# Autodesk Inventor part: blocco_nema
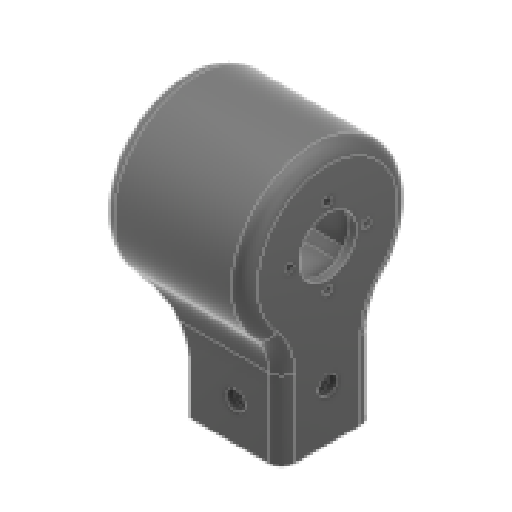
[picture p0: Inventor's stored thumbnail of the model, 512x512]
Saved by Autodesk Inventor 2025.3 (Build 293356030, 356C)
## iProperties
Created: 2026-03
Part Number: blocco_nema
Material: Plastica ABS
Document SubType Name: Modeling
Designer: R5800u
Density: 1.06 g/cm^3
Appearance: Liscia - Nero
Author: R5800u
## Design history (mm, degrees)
sketch "Schizzo1"
  geometry: L1 (18, 18)-(-18, 18); L2 (-18, 18)-(-18, -18); L3 (-18, -18)-(18, -18); L4 (18, -18)-(18, 18); L5 (18, 18)-(-18, -18); L6 (-18, 18)-(18, -18); L7 (10, 10)-(-10, 10); L8 (-10, 10)-(-10, -10); L9 (-10, -10)-(10, -10); L10 (10, -10)-(10, 10); L11 (10, 10)-(-10, -10); L12 (-10, 10)-(10, -10); 1 further point
  constraints: 24 end point, 4 midpoint, 4 parallel, 2 horizontal, 2 perpendicular
  dimensions: "d0" = 36 distance of L3.end L2.end; "d1" = 36 distance of L2.end L1.end; "d2" = 20 distance of L9.end L8.end; "d3" = 20 distance of L8.end L7.end
extrude "Estrusione1" new body sketch "Schizzo1" distance "d4" = 40; taper "d5" = 0 deg
sketch "Schizzo2" dims "d6" = 65
  geometry: L1 (40, -18)-(40, 18) reference; L2 (40, 0)-(87.596, 0); L3 (88.06, 21)-(46.06, 21); L4 (46.06, 21)-(46.06, -21); L5 (46.06, -21)-(88.06, -21); L6 (88.06, -21)-(88.06, 21); L7 (88.06, 21)-(46.06, -21); L8 (46.06, 21)-(88.06, -21); 3 further points
  constraints: 14 end point, 3 midpoint, 2 horizontal, 2 parallel, 1 perpendicular, 1 point on line, 3 other
  dimensions: "d7" = 42 distance of L5.end L4.end; "d8" = 42 distance of L4.end L3.end
extrude "Estrusione2" join sketch "Schizzo2" stored distance "d9" = 36; taper "d10" = 0 deg
sketch "Schizzo3"
  geometry: L1 (-3, 88.06)-(39, 88.06) reference; L2 (39, 88.06)-(39, 46.06) reference; L3 (39, 46.06)-(-3, 46.06) reference; L4 (-3, 46.06)-(-3, 88.06) reference; L5 (0, 0)-(36, 0) reference; L6 (36, 0)-(36, 40) reference; L7 (0, 0)-(0, 40) reference; A1 r 32.5 centre (18, 67.06) between (36, 40) and (0, 40) reference; 3 further points
  constraints: 1 coincident, 3 other
extrude "Estrusione3" join sketch "Schizzo3" distance "d11" = 20; taper "d12" = 0 deg
fillet "Raccordo1" dims "d13" = 20
sketch "Schizzo4"
  geometry: L1 (-3, 88.06)-(39, 88.06) reference; L2 (39, 88.06)-(39, 46.06) reference; L3 (39, 46.06)-(-3, 46.06) reference; L4 (-3, 46.06)-(-3, 88.06) reference; L5 (0, 0)-(36, 0) reference; L6 (36, 0)-(36, 30.835) reference; L7 (0, 0)-(0, 30.835) reference; C1 r 11.25 at (18, 67.06); C2 r 1.621 at (18, 82.06) reference; C3 r 1.621 at (3, 67.06) reference; C4 r 1.621 at (18, 52.06) reference; C5 r 1.621 at (33, 67.06) reference; A1 r 20 centre (56, 30.835) between (41.524, 44.635) and (36, 30.835) reference; A2 r 32.5 centre (18, 67.06) between (41.524, 44.635) and (-5.524, 44.635) reference; A3 r 20 centre (-20, 30.835) between (0, 30.835) and (-5.524, 44.635) reference; 1 further point
  constraints: 1 centre point, 1 coincident
  dimensions: "d14" = 22.5 diameter of C1
  node "Linea chiusa proiettata2"
  node "Riferimento1"
  node "Riferimento2"
  node "Riferimento3"
  node "Riferimento4"
node "Piano di lavoro1"
extrude "Estrusione4" join sketch "Schizzo4" stored distance "d15" = 20; taper "d16" = 0 deg
fillet "Raccordo2" dims "d17" = 5
chamfer "Smusso3" distance "d24" = 3; stored, may be unused: second distance "d25" = 2, angle "d26" = 45 deg
fillet "Raccordo3" dims "d27" = 4
sketch "Schizzo5"
  geometry: L1 (22.037, -30.835)-(22.037, -15.835)
  constraints: 2 end point, 1 vertical
  dimensions: "d28" = 15 distance of L1.start L1.end
hole "Foro1" sketch "Schizzo5" at (22.037, -15.835) diameter "d29" = 4.3; stored, may be unused: countersink angle "d33" = 90 deg, drill point angle "d35" = 118 deg; dims "d30" = 6, "d31" = 7.5, "d32" = 3, "d34" = 8
sketch "Schizzo6"
  geometry: C1 r 2.15 at (13, -15.835) reference; 2 further points
  constraints: 1 coincident
hole "Foro2" sketch "Schizzo6" at (13, -15.835) diameter "d36" = 4.3; stored, may be unused: countersink angle "d40" = 90 deg, drill point angle "d42" = 118 deg; dims "d37" = 6, "d38" = 7.5, "d39" = 3, "d41" = 8
sketch "Schizzo7"
  geometry: L1 (0, -67.06)-(0, -47.06)
  constraints: 2 end point, 1 vertical
  dimensions: "d43" = 20 distance of L1.start L1.end
hole "Foro3" sketch "Schizzo7" at (0, -47.06) diameter "d44" = 4.3; stored, may be unused: countersink angle "d48" = 90 deg, drill point angle "d50" = 118 deg; dims "d45" = 6, "d46" = 7.5, "d47" = 3, "d49" = 8
chamfer "Smusso4" distance "d51" = 2; stored, may be unused: second distance "d52" = 2, angle "d53" = 45 deg
node "Solido1"
node "Linea chiusa proiettata1"
